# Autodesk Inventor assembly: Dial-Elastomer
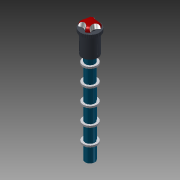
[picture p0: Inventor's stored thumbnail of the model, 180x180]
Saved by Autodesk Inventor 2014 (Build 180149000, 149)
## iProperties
Shininess: 64.0
Length Units: 11272
Angle Units: 11279
Time Units: 11290
Mass Units: 11286
Length Display Precision: 3
Angle Display Precision: 2
Compacted: True
Created: 2001-11
Part Number: Dial-Elastomer
Document SubType Name: Assembly
Designer: Autodesk, Inc.
Mass: 34.1122 g
Surface Area: 233.654 cm^2
Volume: 34.1122 cm^3
Density: 1 g/cm^3
Density: 0.0
Volumn: 0.0
Area: 0.0
PropertySet Name: Model Information
Control State: 0
Master: False
Checked Out: False
Author: Autodesk, Inc.
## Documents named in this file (7)
- C:\Users\iTools\Desktop\tutorial files\Assembly FEA 3\Components\Dial-Elastomer.iam
- C:\Users\iTools\Desktop\tutorial files\Assembly FEA 3\Components\Dial-cap.ipt
- C:\Users\iTools\Desktop\tutorial files\Assembly FEA 3\Components\Dial-Cover.ipt
- C:\Users\iTools\Desktop\tutorial files\Assembly FEA 3\Components\Dial.ipt
- C:\Users\iTools\Desktop\tutorial files\Assembly FEA 3\Components\Elastomer.ipt
- C:\Users\iTools\Desktop\tutorial files\Assembly FEA 3\Components\Spacer.ipt
- C:\Users\iTools\Desktop\tutorial files\Assembly FEA 3\Components\Dial-Base.ipt
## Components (15 placed, 6 different names)
1. PART1_1 — Insert:14, Mate:1, Mate:2, Mate:3
2. Elastomer:1 — Insert:3, Insert:16
3. Dial-Cap — Insert:1, Insert:14
4. Dial-Base:1 — Mate:1, Mate:2, Insert:15, Insert:16
5. Dial:2 — Insert:1, Insert:15
6. Spacer:7 — Insert:3, Insert:5
7. Spacer:8 — Insert:12, Insert:13
8. Elastomer:6 — Insert:5, Insert:6
9. Elastomer:7 — Insert:11, Insert:12
10. Elastomer:8 — Insert:9, Insert:10
11. Elastomer:9 — Insert:7, Insert:8
12. Spacer:9 — Insert:10, Insert:11
13. Spacer:10 — Insert:8, Insert:9
14. Spacer:11 — Insert:6, Insert:7
15. Elastomer:10 — Insert:13
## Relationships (17: Insert 14, Mate 3)
- Insert:1: Dial-Cap ↔ Dial:2
- Insert:3: Elastomer:1 ↔ Spacer:7
- Insert:5: Spacer:7 ↔ Elastomer:6
- Insert:6: Elastomer:6 ↔ Spacer:11
- Insert:7: Elastomer:9 ↔ Spacer:11
- Insert:8: Elastomer:9 ↔ Spacer:10
- Insert:9: Elastomer:8 ↔ Spacer:10
- Insert:10: Elastomer:8 ↔ Spacer:9
- Insert:11: Elastomer:7 ↔ Spacer:9
- Insert:12: Spacer:8 ↔ Elastomer:7
- Insert:13: Spacer:8 ↔ Elastomer:10
- Insert:14: PART1_1 ↔ Dial-Cap
- Mate:1: PART1_1 ↔ Dial-Base:1
- Mate:2: PART1_1 ↔ Dial-Base:1
- Insert:15: Dial-Base:1 ↔ Dial:2
- Insert:16: Elastomer:1 ↔ Dial-Base:1
- Mate:3: PART1_1
